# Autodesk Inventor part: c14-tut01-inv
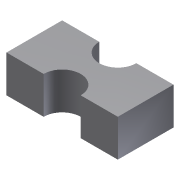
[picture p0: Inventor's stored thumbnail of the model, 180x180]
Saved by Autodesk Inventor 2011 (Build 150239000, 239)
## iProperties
Created: 2010-04
Part Number: c14-tut01-inv
Document SubType Name: Modeling
Designer: CADSoft
Density: 1 g/cm^3
Author: CADSoft
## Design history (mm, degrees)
sketch "Sketch1"
  geometry: L1 (33.666, 15.267)-(33.666, -14.733); L2 (-26.334, -14.733)-(-26.334, 15.267); L3 (-26.334, 15.267)-(-6.334, 15.267); L4 (13.666, 15.267)-(33.666, 15.267); L5 (33.666, -14.733)-(13.666, -14.733); L6 (-6.334, -14.733)-(-26.334, -14.733); A1 r 10 centre (3.666, 15.267) between (-6.334, 15.267) and (13.666, 15.267); A2 r 10 centre (3.666, -14.733) between (13.666, -14.733) and (-6.334, -14.733); 1 further point
  constraints: 12 end point, 5 parallel, 4 equal length, 4 point on circle, 2 centre point, 2 horizontal, 2 horizontal alignment, 2 perpendicular, 1 equal radius
  dimensions: "d0" = 60 distance between parallel lines of L1 L2 (= LEN); "d1" = 30 distance of L2.start L2.end (= WID); "d2" = 10 radius of A1 (= RAD)
extrude "Extrusion1" new body sketch "Sketch1" distance "d3" = 20 (= EXT); taper "d4" = 0 deg
body "Solid1"
other parameters: "LEN" = 60 [user parameter; used in 4 equation terms], "WID" = 30 (= 0.5 x LEN) [user parameter; used in 1 equation term], "RAD" = 10 (= 0.166667 x LEN) [user parameter; used in 1 equation term], "EXT" = 20 (= 0.333333 x LEN) [user parameter; used in 1 equation term]
